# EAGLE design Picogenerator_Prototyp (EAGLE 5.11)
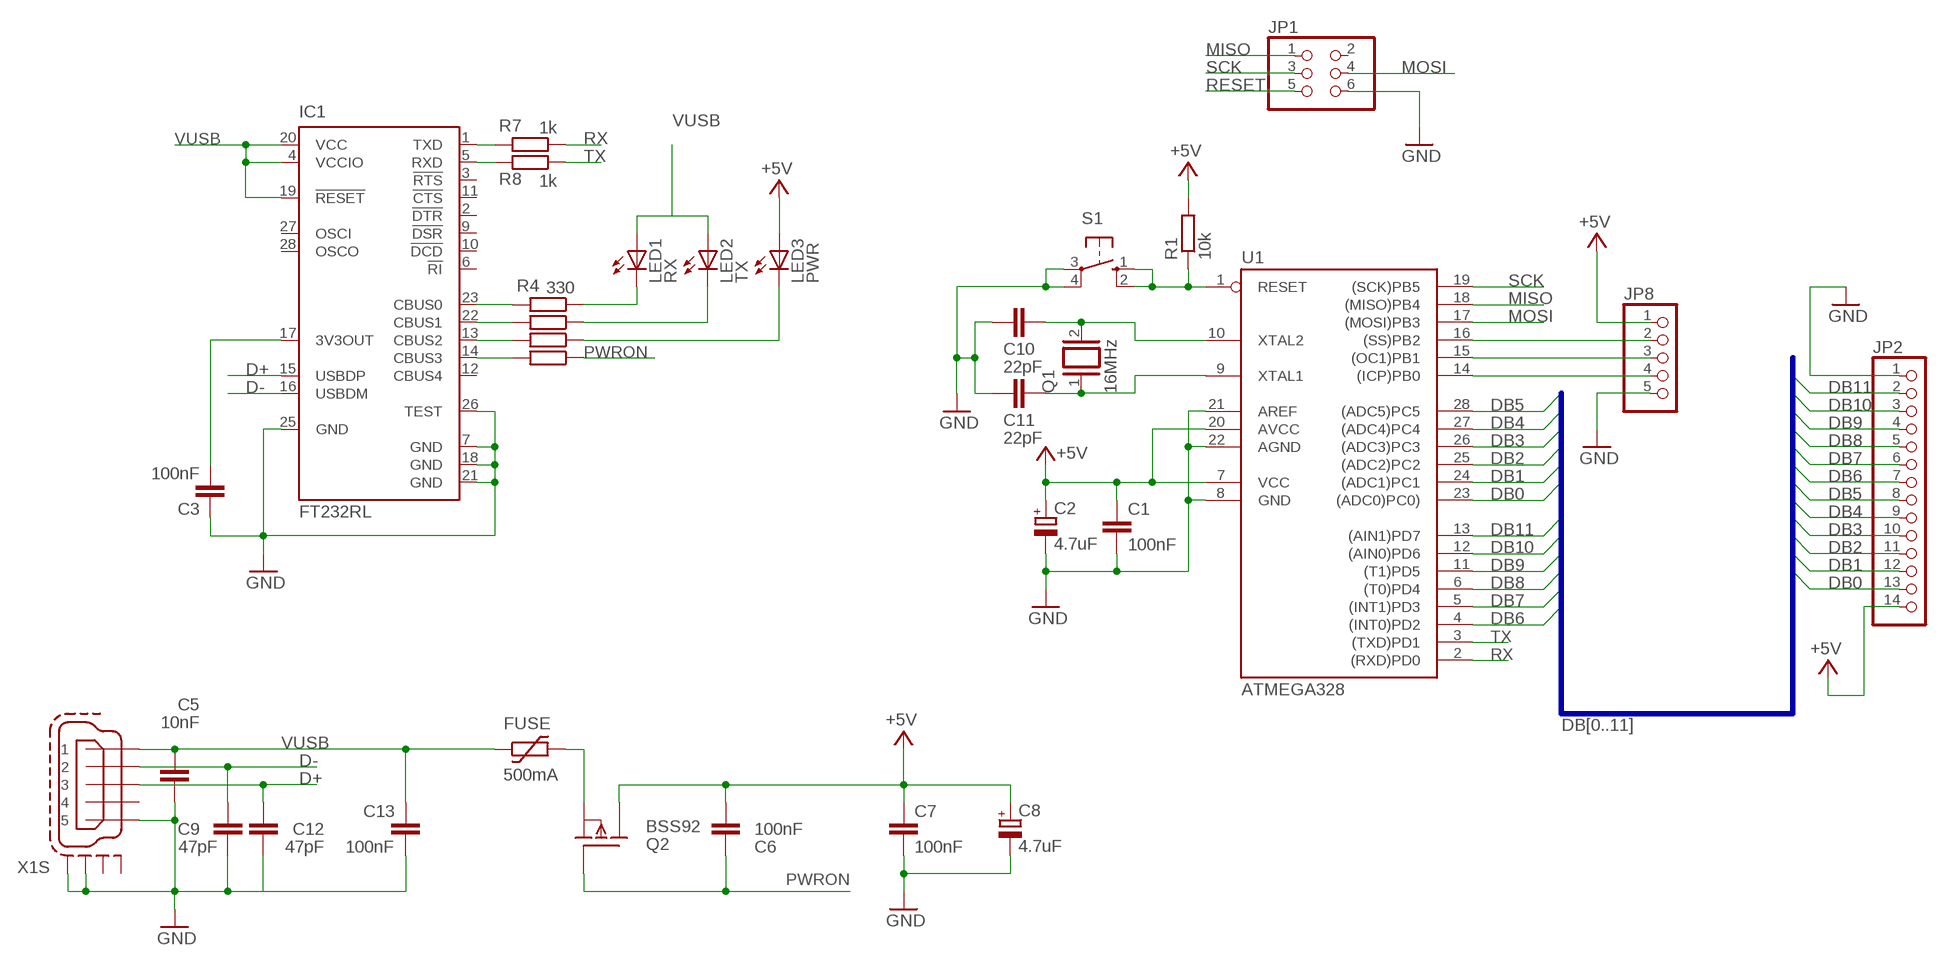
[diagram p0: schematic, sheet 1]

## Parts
C1  100nF  C-EU025-025X050  [C025-025X050]
C2  4.7uF  CPOL-EUE2.5-7  [E2,5-7]
C3  100nF  C-EU025-024X044  [C025-024X044]
C5  10nF  C-EU025-025X050  [C025-025X050]
C6  100nF  C-EU025-025X050  [C025-025X050]
C7  100nF  C-EU025-025X050  [C025-025X050]
C8  4.7uF  CPOL-EUE2.5-6  [E2,5-6]
C9  47pF  C-EU025-024X044  [C025-024X044]
C10  22pF  C-EU025-025X050  [C025-025X050]
C11  22pF  C-EU025-025X050  [C025-025X050]
C12  47pF  C-EU025-024X044  [C025-024X044]
C13  100nF  C-EU025-025X050  [C025-025X050]
FUSE  500mA  NANO_SMD_C  [NANO_SMD_C]
IC1  FT232RL  [SSOP28]
JP1  PINHD-2X03_SMD_PROG  [2X03_SMD_PROG]
JP2  PINHD-1X14_2.54-90°  [1X14/90]
JP8  PINHD-1X5_2.54-90°  [1X05/90]
LED1  RX  LED5MM  [LED5MM]
LED2  TX  LED5MM  [LED5MM]
LED3  PWR  LED5MM  [LED5MM]
Q1  16MHz  XTAL/S  [QS]
Q2  BSS92  [TO92]
R1  10k  R-EU_0207/10  [0207/10]
R2  1k  R-EU_0207/7  [0207/7]
R4  330  R-EU_0207/10  [0207/10]
R5  330  R-EU_0207/10  [0207/10]
R6  330  R-EU_0207/7  [0207/7]
R7  1k  R-EU_0207/15  [0207/15]
R8  1k  R-EU_0207/15  [0207/15]
S1  10-XX  [B3F-10XX]
U1  ATMEGA328  AT90S4433P  [DIL28-3]
X1  MINI-USB-SCHIELD-32005-301  [32005-301]

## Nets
+5V: C1.1 C2.+ C6.2 C7.2 C8.+ JP2.14 JP8.1 LED3.A Q2.2(D) R1.2 U1.7(VCC) U1.20(AVCC)
D+: C12.2 IC1.15(USBDP) X1.3
D-: C9.2 IC1.16(USBDM) X1.2
DB0: JP2.13 U1.23((ADC0)PC0))
DB1: JP2.12 U1.24((ADC1)PC1)
DB2: JP2.11 U1.25((ADC2)PC2)
DB3: JP2.10 U1.26((ADC3)PC3)
DB4: JP2.9 U1.27((ADC4)PC4)
DB5: JP2.8 U1.28((ADC5)PC5)
DB6: JP2.7 U1.4((INT0)PD2)
DB7: JP2.6 U1.5((INT1)PD3)
DB8: JP2.5 U1.6((T0)PD4)
DB9: JP2.4 U1.11((T1)PD5)
DB10: JP2.3 U1.12((AIN0)PD6)
DB11: JP2.2 U1.13((AIN1)PD7)
GND: C1.2 C2.- C3.1 C5.1 C7.1 C8.- C9.1 C10.1 C11.1 C12.1 C13.1 IC1.7(GND) IC1.18(GND) IC1.21(GND) IC1.25(GND) IC1.26(TEST) JP1.6 JP2.1 JP8.5 S1.3(P) S1.4(P1) U1.8(GND) U1.21(AREF) U1.22(AGND) X1.5 X1.M3(S:S3) X1.M4(S:S4)
MISO: JP1.1 U1.18((MISO)PB4)
MOSI: JP1.4 U1.17((MOSI)PB3)
N$2: C10.2 Q1.2 U1.10(XTAL2)
N$3: C11.2 Q1.1 U1.9(XTAL1)
N$5: JP8.2 U1.16((SS)PB2)
N$6: IC1.14(CBUS3) R2.2
N$7: C3.2 IC1.17(3V3OUT)
N$8: LED1.K(C) R4.1
N$9: LED2.K(C) R5.1
N$11: LED3.K(C) R6.1
N$12: IC1.23(CBUS0) R4.2
N$13: IC1.22(CBUS1) R5.2
N$14: IC1.13(CBUS2) R6.2
N$16: IC1.1(TXD) R7.2
N$17: IC1.5(RXD) R8.2
N$29: JP8.3 U1.15((OC1)PB1)
N$30: JP8.4 U1.14((ICP)PB0)
PWRON: C6.1 Q2.1(G) R2.1
RESET: JP1.5 R1.1 S1.1(S) S1.2(S1) U1.1(RESET)
RX: R7.1 U1.2((RXD)PD0)
SCK: JP1.3 U1.19((SCK)PB5)
TX: R8.1 U1.3((TXD)PD1)
VUSB: C5.2 C13.2 FUSE.P$1 IC1.4(VCCIO) IC1.19(!RESET) IC1.20(VCC) LED1.A LED2.A X1.1
VUSB_2: FUSE.P$2 Q2.3(S)
Unconnected: IC1.2(!DTR) IC1.3(!RTS) IC1.6(!RI) IC1.9(!DSR) IC1.10(!DCD) IC1.11(!CTS) IC1.12(CBUS4) IC1.27(OSCI) IC1.28(OSCO) JP1.2 X1.4 X1.M1(S:S1) X1.M2(S:S2)

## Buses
DB[0..11]

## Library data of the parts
C1 C3 C5-C7 C9-C13 = rcl:C-EU: CAPACITOR, European symbol
C2 C8 = rcl:CPOL-EU: POLARIZED CAPACITOR, European symbol
FUSE = polyswitch_smd:NANO_SMD_C: RAYCHEM Polyswitch family nanoSMDC serie
IC1 = ftdichip:FT232R: Source: http://www.ftdichip.com/Documents/DataSheets/DS_FT232R_v104.pdf
JP1 = pinhead-2:PINHD-2X03: PIN HEADER
JP2 = pinhead-1:PINHD-1X14: PIN HEADER
JP8 = pinhead-1:PINHD-1X5: PIN HEADER
LED1-LED3 = led:LED: LED
Q1 = special:XTAL/S: CRYSTAL
Q2 = transistor-fet:BSS92: P-Channel Enhancement MOSFET -200V; -0,15A; 11Ohm
R1 R2 R4-R8 = rcl:R-EU_: RESISTOR, European symbol
S1 = switch-omron:10-XX: OMRON SWITCH; MPN: B3F-1000; OC_FARNELL: 176432; OC_NEWARK: 36M3542
U1 = atmel:AT90S4433: MICROCONTROLLER 4 Kbytes FLASH 128 bytes SRAM 256 bytes EEPROM UART 6-channel 10 bit ADC
X1 = con-cypressindustries:MINI-USB-SCHIELD-: MINI USB-B Conector Source: www.cypressindustries.com

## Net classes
0 default: width 0.152 mm, drill 0.305 mm, clearance 0.152 mm

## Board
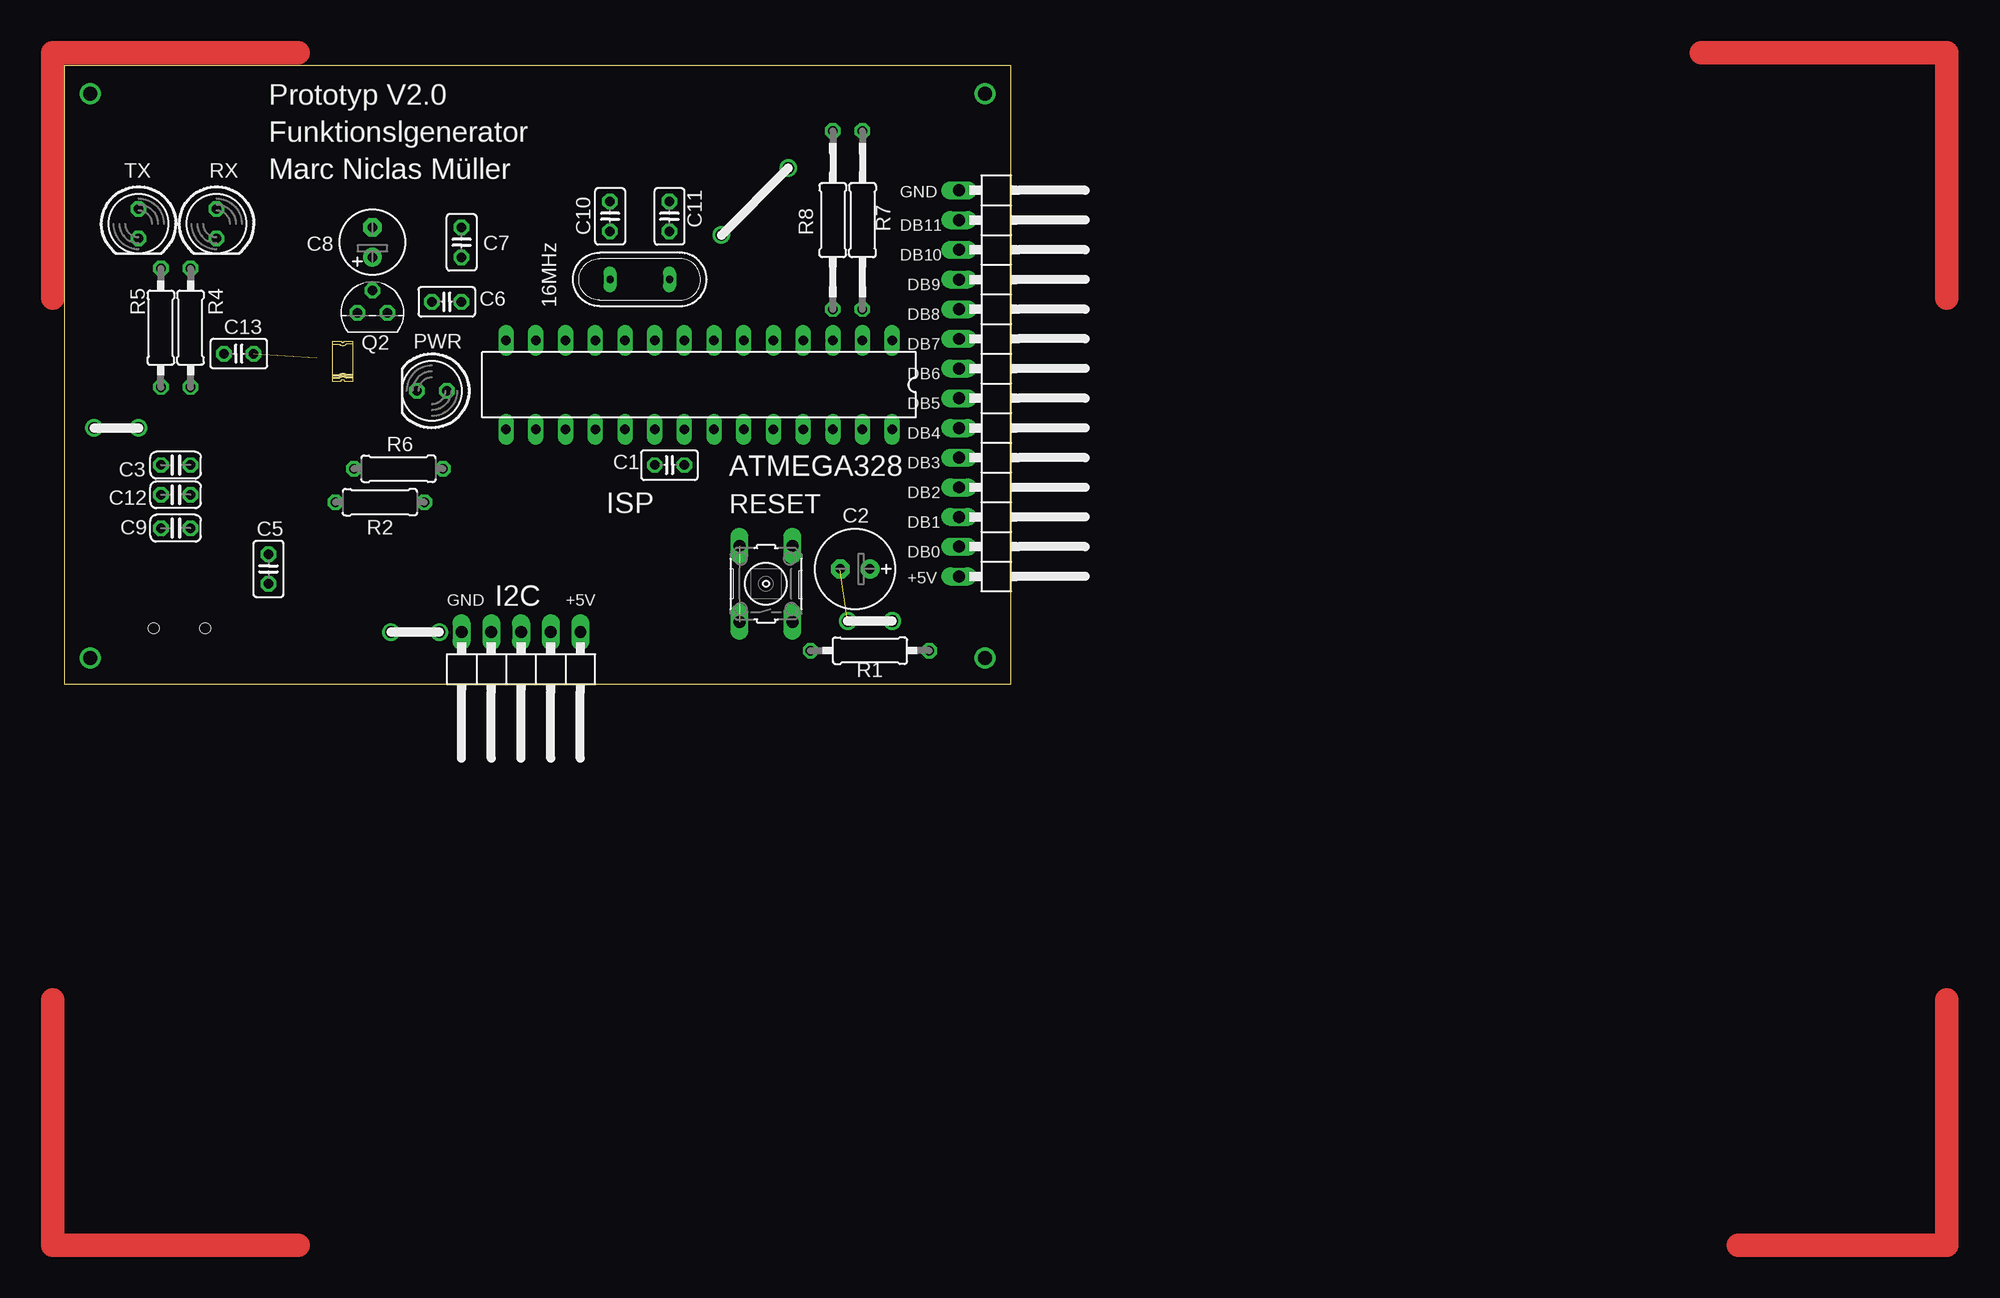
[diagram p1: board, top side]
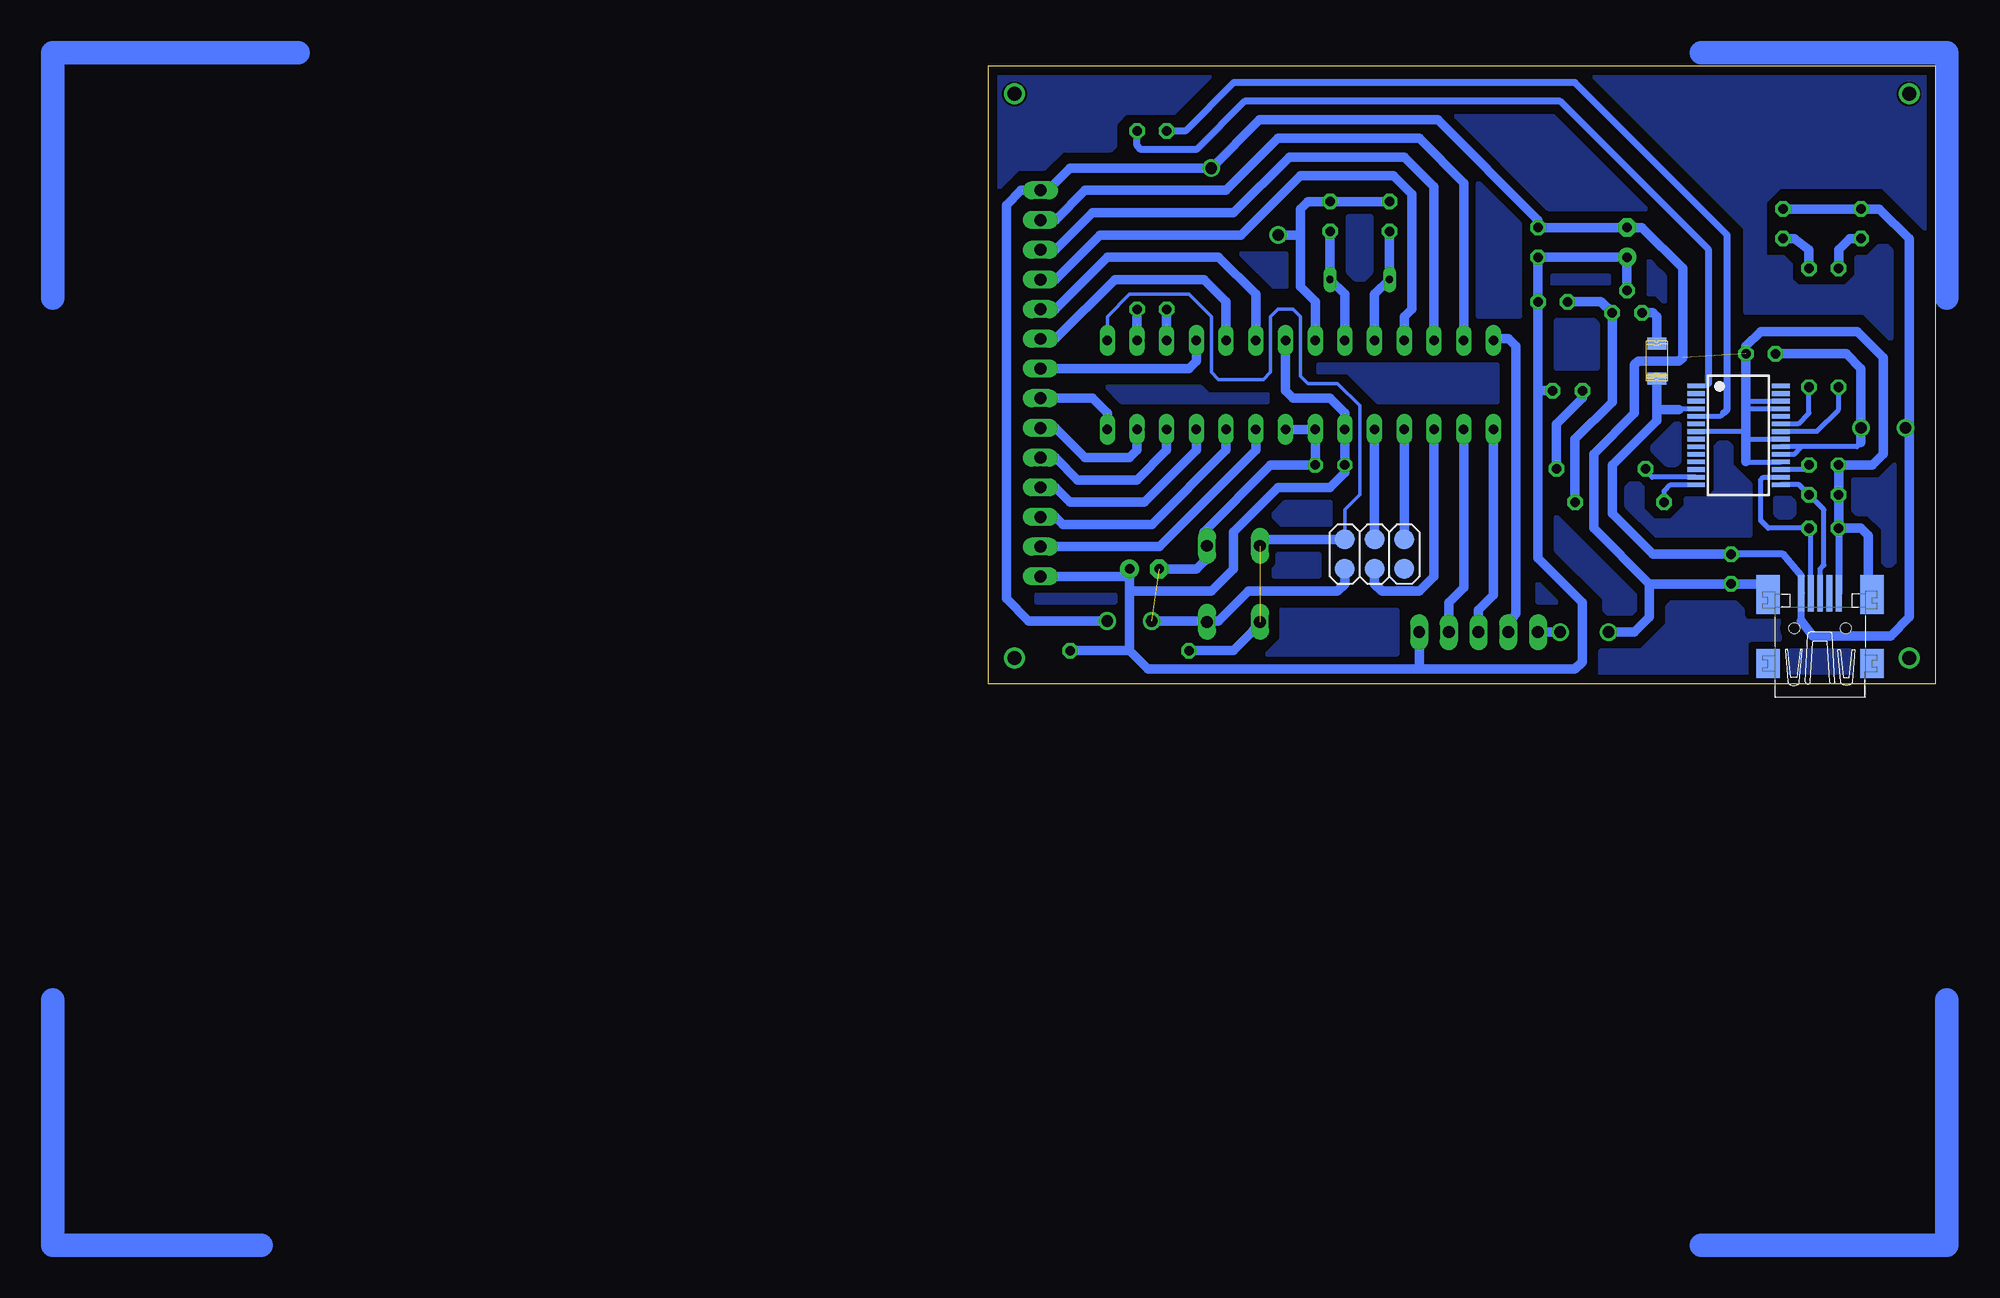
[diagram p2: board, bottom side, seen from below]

Size 80.94 x 52.88 mm. Coordinates in mm from the lower left corner, seen from the top.
Outline: 0,0 80.94,0 80.94,52.88 0,52.88 0,0
Copper layers (1*16): Top 0.035mm / dielectric 1.5mm / Bottom 0.035mm
Design rules "default *": minimum track width 8mil, minimum drill 12mil, track to track 6mil, track to pad 6mil, pad to pad 6mil, via to via 6mil, smd to smd 6mil, copper to edge 30mil, drill to drill 12mil, minimum pad ring 10mil, minimum via ring 10mil, stop-mask expansion 1mil, vias tented up to drill 0mil, thermal gap 10mil

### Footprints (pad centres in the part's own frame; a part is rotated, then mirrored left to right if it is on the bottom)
C025-025X050 = drill 0.813 octagon: 1 -1.27,0; 2 1.27,0
E2,5-7 = drill 0.813 pad 1.6 round: + -1.27,0 | drill 0.813 pad 1.6 octagon: - 1.27,0
C025-024X044 = drill 0.813 octagon: 1 -1.27,0; 2 1.27,0
E2,5-6 = drill 0.813 pad 1.6 round: + -1.27,0 | drill 0.813 pad 1.6 octagon: - 1.27,0
NANO_SMD_C = smd 1 x 1.6: P$1 1.5,0; P$2 -1.5,0
SSOP28 = smd 0.4 x 1.5: 1 -4.225,-3.625; 2 -3.575,-3.625; 3 -2.925,-3.625; 4 -2.275,-3.625; 5 -1.625,-3.625; 6 -0.975,-3.625; 7 -0.325,-3.625; 8 0.325,-3.625; 9 0.975,-3.625; 10 1.625,-3.625; 11 2.275,-3.625; 12 2.925,-3.625; 13 3.575,-3.625; 14 4.225,-3.625; 15 4.225,3.625; 16 3.575,3.625; 17 2.925,3.625; 18 2.275,3.625; 19 1.625,3.625; 20 0.975,3.625; 21 0.325,3.625; 22 -0.325,3.625; 23 -0.975,3.625; 24 -1.625,3.625; 25 -2.275,3.625; 26 -2.925,3.625; 27 -3.575,3.625; 28 -4.225,3.625
2X03_SMD_PROG = smd 1.7 x 1.7: 1 -2.54,-1.27; 2 -2.54,1.27; 3 0,-1.27; 4 0,1.27; 5 2.54,-1.27; 6 2.54,1.27
1X14/90 = drill 1.016 long: 1 -16.51,-3.81; 2 -13.97,-3.81; 3 -11.43,-3.81; 4 -8.89,-3.81; 5 -6.35,-3.81; 6 -3.81,-3.81; 7 -1.27,-3.81; 8 1.27,-3.81; 9 3.81,-3.81; 10 6.35,-3.81; 11 8.89,-3.81; 12 11.43,-3.81; 13 13.97,-3.81; 14 16.51,-3.81
1X05/90 = drill 1.016 long: 1 -5.08,-3.81; 2 -2.54,-3.81; 3 0,-3.81; 4 2.54,-3.81; 5 5.08,-3.81
LED5MM = drill 0.813 octagon: A -1.27,0; K 1.27,0
QS = drill 0.61 long: 1 -2.54,0; 2 2.54,0
TO92 = drill 0.813 octagon: 1 1.27,0; 2 0,1.905; 3 -1.27,0
0207/10 = drill 0.813 octagon: 1 -5.08,0; 2 5.08,0
0207/7 = drill 0.813 octagon: 1 -3.81,0; 2 3.81,0
0207/15 = drill 0.813 octagon: 1 -7.62,0; 2 7.62,0
B3F-10XX = drill 1.016 long: 1 -3.251,2.261; 2 3.251,2.261; 3 -3.251,-2.261; 4 3.251,-2.261
DIL28-3 = drill 0.813 long: 1 -16.51,-3.81; 2 -13.97,-3.81; 3 -11.43,-3.81; 4 -8.89,-3.81; 5 -6.35,-3.81; 6 -3.81,-3.81; 7 -1.27,-3.81; 8 1.27,-3.81; 9 3.81,-3.81; 10 6.35,-3.81; 11 8.89,-3.81; 12 11.43,-3.81; 13 13.97,-3.81; 14 16.51,-3.81; 15 16.51,3.81; 16 13.97,3.81; 17 11.43,3.81; 18 8.89,3.81; 19 6.35,3.81; 20 3.81,3.81; 21 1.27,3.81; 22 -1.27,3.81; 23 -3.81,3.81; 24 -6.35,3.81; 25 -8.89,3.81; 26 -11.43,3.81; 27 -13.97,3.81; 28 -16.51,3.81
32005-301 = smd 3.1 x 0.5: 1 3,1.6; 2 3,0.8; 3 3,0; 4 3,-0.8; 5 3,-1.6 | smd 2.5 x 2: M1 -3,-4.45; M2 -3,4.45 | smd 3.3 x 2: M3 2.9,4.45; M4 2.9,-4.45 | hole 0.9: 0,2.2; 0,-2.2

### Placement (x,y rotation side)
C1  51.75,18.73 0 top
C2  67.63,9.84 180 top
C3  9.53,18.73 0 top
C5  17.46,9.84 90 top
C6  32.7,32.7 0 top
C7  33.97,37.78 270 top
C8  26.35,37.78 90 top
C9  9.53,13.34 0 top
C10  46.67,40.01 270 top
C11  51.75,40.01 270 top
C12  9.53,16.19 0 top
C13  14.92,28.26 180 top
FUSE  23.81,27.62 270 bottom
IC1  16.83,21.27 270 bottom
JP1  47.94,11.11 180 bottom
JP2  80.33,25.72 270 top
JP8  39.05,0.63 180 top
LED1  13.02,39.37 270 top
LED2  6.35,39.37 270 top
LED3  31.43,25.08 180 top
Q1  49.21,34.61 180 top
Q2  26.35,31.75 0 top
R1  68.9,2.86 0 top
R2  26.99,15.56 180 top
R4  10.79,30.48 270 top
R5  8.26,30.48 270 top
R6  28.57,18.41 180 top
R7  68.26,39.69 90 top
R8  65.72,39.69 90 top
S1  60.01,8.57 90 top
U1  54.29,25.59 180 top
X1  9.84,4.76 90 bottom

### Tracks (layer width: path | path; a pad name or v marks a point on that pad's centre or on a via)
+5V
  Bottom 0.813: 68.9,9.21 C2.+ | 68.9,9.21 JP2.14 | U1.7 55.56,25.08 54.93,24.45 51.75,24.45 50.48,23.18 U1.20 C1.1 50.48,18.1 51.75,16.83 56.2,16.83 60.01,13.02 60.01,9.84 61.91,7.94 68.9,7.94 | 68.9,2.86 R1.2 | 68.9,2.86 67.31,1.27 44.13,1.27 | 68.9,2.86 68.9,7.94 | 68.9,7.94 68.9,9.21 | Q2.2 C8.+ C7.2 C6.2 33.97,25.08 | 44.13,1.27 30.8,1.27 30.16,1.91 30.16,6.98 33.97,10.79 33.97,25.08 | 44.13,1.27 JP8.1 | 33.97,25.08 LED3.A
D+
  Bottom 0.406: IC1.15 11.65,17.05 C12.2 9.53,14.92 9.53,10.16 9.84,9.84 X1.3
D-
  Bottom 0.406: IC1.16 14.69,17.7 14.92,17.46 14.92,13.97 14.29,13.34 C9.2 10.64,13.18 X1.2
DB0
  Bottom 0.813: JP2.13 66.36,11.75 58.1,20 U1.23
DB1
  Bottom 0.813: U1.24 60.64,20 66.99,13.65 74.61,13.65 75.25,14.29 JP2.12
DB2
  Bottom 0.813: JP2.11 75.25,16.83 73.98,15.56 67.63,15.56 63.18,20 U1.25
DB3
  Bottom 0.813: U1.26 65.72,20 68.26,17.46 73.34,17.46 75.25,19.37 JP2.10
DB4
  Bottom 0.813: JP2.9 75.25,21.91 72.71,19.37 68.9,19.37 68.26,20 U1.27
DB5
  Bottom 0.813: U1.28 70.8,23.18 72.07,24.45 JP2.8
DB6
  Bottom 0.813: JP2.7 63.82,26.99 63.18,27.62 U1.4
DB7
  Bottom 0.813: JP2.6 75.25,29.53 70.17,34.61 62.55,34.61 60.64,32.7 U1.5
DB8
  Bottom 0.813: U1.6 58.1,33.34 61.28,36.51 70.8,36.51 75.25,32.07 JP2.5
DB9
  Bottom 0.813: JP2.4 75.25,34.61 71.44,38.42 59.37,38.42 54.29,43.5 46.35,43.5 44.77,41.91 44.77,32.07 45.4,31.43 U1.11
DB10
  Bottom 0.813: U1.12 42.86,42.54 45.4,45.09 55.24,45.09 60.01,40.32 72.07,40.32 75.25,37.15 JP2.3
DB11
  Bottom 0.813: JP2.2 75.25,39.69 72.71,42.23 60.64,42.23 56.2,46.67 44.13,46.67 40.32,42.86 U1.13
GND  (via drill 1)  (2 unrouted)
  Top 0.813: v70.8,5.4 v66.99,5.4 | v61.91,44.13 v56.2,38.42 | v27.94,4.45 v32.07,4.45
  Bottom 0.406: IC1.7 17.15,21.6 16.19,21.59 | IC1.18 15.93,19 16.19,19.05 | IC1.21 15.87,20.95 16.19,21.27 | IC1.26 15.94,24.2 16.19,24.45 | IC1.25 15.93,23.55 16.19,23.81
  Bottom 0.61: X1.5 8.24,13.32 C9.1
  Bottom 0.813: C10.1 C11.1 53.66,41.27 54.29,40.64 54.29,38.42 | U1.8 53.02,32.7 54.29,33.97 54.29,38.42 | U1.22 U1.21 C1.2 56.83,18.73 62.55,13.02 62.55,12.74 S1.4 62.55,11.54 62.55,10.48 63.18,9.84 C2.- | JP1.6 50.48,8.57 51.12,7.94 58.74,7.94 61.28,5.4 62.19,5.4 S1.3 62.34,5.4 v66.99,5.4 | v70.8,5.4 77.53,5.4 79.44,7.3 79.44,40.96 78.17,42.23 JP2.1 75.88,42.23 73.98,44.13 v61.91,44.13 57.78,48.26 42.55,48.26 33.97,39.69 C7.1 C8.- 25.08,39.05 21.59,35.56 21.59,27.94 21.91,27.62 25.4,27.62 25.72,27.3 25.72,23.18 29.21,19.68 29.21,13.34 24.45,8.57 | v56.2,38.42 54.29,38.42 | 16.19,19.05 16.19,21.27 16.19,21.59 16.19,23.81 16.19,24.45 C13.1 16.19,28.89 14.92,30.16 6.67,30.16 4.45,27.94 4.45,19.68 5.4,18.73 C3.1 C12.1 C9.1 6.35,13.34 5.71,12.7 5.71,7.98 X1.M4 | X1.M3 14.57,8.57 C5.1 24.45,8.57 | v32.07,4.45 JP8.5 | v27.94,4.45 25.72,4.45 24.45,5.71 24.45,8.57
MISO
  Bottom 0.813: JP1.1 U1.18
MOSI
  Bottom 0.813: JP1.4 47.94,8.57 47.31,7.94 44.13,7.94 42.86,9.21 U1.17
N$1
  pour Bottom: 3.81,37.15 3.81,29.53 6.03,31.75 16.19,31.75 16.19,36.51 13.02,36.51 12.38,35.88 12.38,34.61 11.75,33.97 7.62,33.97 6.67,34.93 6.67,36.51 5.71,36.51 4.76,37.46 4.13,37.46
N$2
  Bottom 0.813: U1.10 47.94,33.34 Q1.2 C10.2
N$3
  Bottom 0.813: U1.9 50.48,33.34 Q1.1 C11.2
N$4
  pour Bottom: 0.64,52.39 0.64,38.73 4.45,42.54 13.34,42.54 14.61,41.27 14.61,36.51 16.19,36.51 16.19,39.05 29.53,52.39
N$5
  Bottom 0.813: JP8.2 41.59,6.98 40.32,8.25 U1.16
N$6
  Bottom 0.406: R2.2 23.18,16.51 22.64,17.05 IC1.14
N$7
  Bottom 0.406: IC1.17 11.18,18.35 C3.2
N$8
  Bottom 0.813: R4.1 10.79,37.15 12.06,38.1 LED1.K
N$9
  Bottom 0.813: LED2.K 7.3,38.1 8.26,37.15 R5.1
N$10
  pour Bottom: 40.96,48.58 32.7,48.58 24.77,40.64 33.02,40.64
N$11
  Bottom 0.813: LED3.K 30.16,24.45 32.38,22.23 R6.1
N$12
  Bottom 0.406: IC1.23 11.72,22.25 10.79,23.18 R4.2
N$13
  Bottom 0.406: R5.2 8.26,23.49 10.15,21.6 IC1.22
N$14
  Bottom 0.406: IC1.13 24.21,17.7 R6.2
N$15
  pour Bottom: 39.05,42.86 35.56,39.37 35.56,31.43 39.05,31.43
N$16
  Bottom 0.406: IC1.1 19.59,25.5 19.37,25.72
  Bottom 0.61: 19.37,25.72 19.37,37.15 32.07,49.85 59.05,49.85 63.18,45.72 67.94,45.72 68.26,46.04 R7.2
N$17
  Bottom 0.406: IC1.5 18.38,22.9 18.1,23.18
  Bottom 0.61: 18.1,23.18 17.78,23.49 17.78,38.42 30.8,51.43 60.01,51.43 64.14,47.31 R8.2
N$18
  pour Bottom: 48.26,40.01 48.26,35.24 48.9,34.61 49.53,34.61 50.16,35.24 50.16,40.01
N$19
  pour Bottom: 55.56,36.83 55.56,33.97 56.52,33.97 59.05,36.51 59.37,36.83
N$20
  pour Bottom: 37.47,27.3 37.47,24.13 47.62,24.13 50.16,26.67 52.7,26.67 52.7,27.3
N$21
  pour Bottom: 57.15,24.76 57.15,24.13 69.53,24.13 70.8,25.4 62.87,25.4 62.23,24.76
N$22
  pour Bottom: 46.04,6.35 46.04,2.54 57.15,2.54 55.88,3.81 55.88,6.35
N$23
  pour Bottom: 52.7,11.11 52.7,9.21 56.52,9.21 56.52,9.84 56.2,10.16 56.2,11.11
N$24
  pour Bottom: 51.75,15.56 51.75,13.65 55.88,13.65 56.52,14.29 56.52,14.6 55.56,15.56
N$25
  pour Bottom: 70.17,7.62 70.17,6.98 76.83,6.98 76.83,7.62
N$26
  pour Bottom: 12.38,15.88 13.65,15.88 13.65,14.6 13.34,14.29 12.38,14.29 12.06,14.6 12.06,15.56
N$27
  pour Bottom: 15.88,17.15 15.88,12.7 23.81,12.7 26.35,15.24 26.35,16.83 26.04,17.15 25.4,17.15 25.08,16.83 25.08,14.92 24.13,13.97 22.54,13.97 21.27,15.24 21.27,15.88 19.37,15.88 18.73,16.51 18.73,20.32 18.41,20.64 17.78,20.64 17.46,20.32 17.46,18.73
N$28
  pour Bottom: 21.91,22.23 21.91,19.05 22.23,18.73 22.86,18.73 24.13,20 24.13,20.32 22.23,22.23
N$29
  Bottom 0.813: JP8.3 39.05,6.35 37.78,7.62 U1.15
N$30
  Bottom 0.813: JP8.4 36.51,5.08 35.88,6.03 35.88,28.89 36.51,29.53 37.66,29.53 U1.14
N$31
  Top 2: 20,-47.99 -1,-47.99 -1,-26.99
N$32
  Top 2: 143.18,-47.99 161,-47.99 161,-26.99
N$33
  Top 2: 20,54.01 -1,54.01 -1,33.01
N$34
  Top 2: 161,33.01 161,54.01 140,54.01
N$35
  Bottom 2: 20,-47.99 -1,-47.99 -1,-26.99
N$36
  Bottom 2: 143.18,-47.99 161,-47.99 161,-26.99
N$37
  Bottom 2: 20,54.01 -1,54.01 -1,33.01
N$38
  Bottom 2: 161,33.01 161,54.01 140,54.01
N$39
  pour Bottom: 6.99,17.46 6.99,14.92 6.67,14.6 5.71,14.6 4.45,13.34 4.45,10.48 4.13,10.16 3.81,10.16 3.49,10.48 3.49,18.73 4.76,17.46
N$40
  pour Bottom: 24.13,35.88 23.18,34.93 23.18,32.7 23.81,33.34 24.45,33.34 24.45,36.2
N$41
  pour Bottom: 27.94,34.93 27.94,34.29 32.7,34.29 32.7,34.93
N$42
  pour Bottom: 29.21,31.12 28.89,30.8 28.89,26.99 32.38,26.99 32.38,31.12
N$43
  pour Bottom: 7.3,2.86 7.3,0.63 12.38,0.63 12.38,2.86
N$44
  pour Bottom: 13.34,5.4 13.34,3.81 15.88,3.81 16.19,3.49 16.19,0.63 28.57,0.63 28.57,2.86 25.08,2.86 22.86,5.08 22.86,6.67 22.54,6.98 17.14,6.98 16.51,6.35 16.51,5.71 16.19,5.4
N$45
  pour Bottom: 25.72,7.62 25.72,6.35 26.04,6.03 27.94,6.03 28.26,6.35 28.26,7.3 32.38,11.43 32.38,14.29
N$46
  pour Bottom: 80.64,52.7 80.64,42.54 80.01,42.54 78.42,44.13 76.2,44.13 74.61,45.72 70.48,45.72 70.17,46.04 70.17,47.94 69.22,48.9 65.09,48.9 61.28,52.7
N$47
  pour Bottom: 33.97,8.57 32.38,6.98 33.97,6.98 33.97,8.25
N$118  (via drill 1.2)
  other vias: 78.74,2.22
N$172  (via drill 1.2)
  other vias: 2.22,50.48
N$226  (via drill 1.2)
  other vias: 78.74,50.48
N$253  (via drill 1.2)
  other vias: 2.22,2.22
PWRON
  Bottom 0.813: C6.1 28.57,32.7 Q2.1 27.62,24.13 30.8,20.95 R2.1
RESET  (1 unrouted)
  Bottom 0.305: U1.1 70.8,31.43 68.9,33.34 63.82,33.34 61.91,31.43 61.91,26.67 61.28,26.04 57.47,26.04 56.83,26.67 56.83,31.43 56.2,32.07 54.93,32.07 54.29,31.43 54.29,26.35 53.66,25.72 51.12,25.72 49.21,23.81 49.21,16.19 50.48,14.92 JP1.5
  Bottom 0.813: 57.67,12.38 S1.2 57.75,12.38 JP1.5 | S1.1 58.38,4.48 60.01,2.86 R1.1
RX
  Bottom 0.813: U1.2 R7.1
SCK
  Bottom 0.813: JP1.3 U1.19
TX
  Bottom 0.813: U1.3 R8.1
VUSB  (via drill 1)
  Top 0.813: v2.54,21.91 v6.35,21.91
  Bottom 0.406: 11.43,20.3 IC1.20 | 11.43,20.3 6.69,20.3 6.35,20.64 | IC1.19 12.08,19.65 11.43,20.3 | IC1.4 21.86,23.55 21.91,23.49
  Bottom 0.61: C5.2 13.02,11.11 11.44,9.22 X1.1 11.44,5.41
  Bottom 0.813: C5.2 24.13,11.11 27.62,14.6 27.62,18.73 23.81,22.54 23.81,23.49 | 11.44,5.41 10.48,4.13 3.81,4.13 2.22,5.71 2.22,21.91 v2.54,21.91 2.22,22.23 2.22,38.1 4.76,40.64 LED2.A LED1.A | C13.2 7.62,28.26 6.35,26.99 v6.35,21.91 6.35,20.64 | 23.81,23.49 FUSE.P$1 | 23.81,23.49 21.91,23.49
VUSB_2
  Bottom 0.813: FUSE.P$2 23.81,31.43 24.13,31.75 Q2.3

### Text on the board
tNames: Prototyp V2.0 | Funktionslgenerator | Marc Niclas Müller | GND | DB11 | DB10 | DB9 | DB8 | DB7 | DB6 | DB5 | DB4 | ATMEGA328 | DB3 | DB2 | ISP | RESET | DB1 | DB0 | +5V | GND | I2C | +5V
214bmp: D:/SmartProjects/Snc/a4_bn_logo2.bmp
